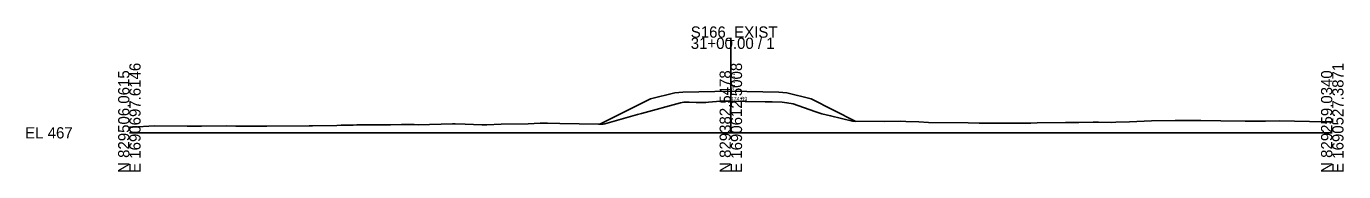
# Model space of a CAD drawing. Extents: x 1621104 to 1621433, y 1192880 to 1199414.
# Drawn here: x 1621104.2 to 1621432.7, y 1196379.5 to 1196415.8 of the extents above; entities that cross this region are included whole.
import ezdxf

# ---------------------------------------------------------------- set-up
doc = ezdxf.new("R2010")
doc.units = 0
for name, color, linetype in [('RD_GPK_XS_Cell', 7, 'Continuous'), ('RD_XS_EarthShd', 7, 'Continuous'), ('RD_XS_ExGround', 7, 'Continuous'), ('RD_XS_Pave', 7, 'Continuous'), ('RD_XS_TieSlope', 7, 'Continuous'), ('RD_XS_TX_Elev_EX', 7, 'Continuous'), ('RD_XS_TX_Elev_PR', 7, 'Continuous')]:
    doc.layers.add(name, color=color, linetype=linetype)

msp = doc.modelspace()

# ---------------------------------------------------------------- linework, layer by layer
at = {"layer": 'RD_GPK_XS_Cell'}
for p, q in [((1621279.86, 1196389.24), (1621279.86, 1196412.99)), ((1621129.86, 1196389.24), (1621279.86, 1196389.24)), ((1621279.86, 1196389.24), (1621429.86, 1196389.24))]:
    msp.add_line(p, q, dxfattribs=at)
at = {"layer": 'RD_XS_EarthShd'}
for p, q in [((1621267.86, 1196399.37), (1621265.86, 1196399.21)), ((1621291.86, 1196399.37), (1621293.86, 1196399.21))]:
    msp.add_line(p, q, dxfattribs=at)
at = {"layer": 'RD_XS_ExGround'}
msp.add_lwpolyline([(1621129.86, 1196390.64), (1621130.61, 1196390.68), (1621136.01, 1196390.97), (1621144.31, 1196390.87), (1621145.07, 1196390.87), (1621147.84, 1196390.89), (1621153.99, 1196390.95), (1621156.41, 1196390.92), (1621159.51, 1196390.9), (1621161.89, 1196390.88), (1621164.16, 1196390.92), (1621174.73, 1196390.96), (1621175.56, 1196390.99), (1621181.61, 1196391.1), (1621182.72, 1196391.15), (1621185.7, 1196391.18), (1621186.6, 1196391.24), (1621194.96, 1196391.25), (1621197.74, 1196391.28), (1621200.89, 1196391.31), (1621201.85, 1196391.26), (1621210.45, 1196391.48), (1621211.12, 1196391.48), (1621213.64, 1196391.37), (1621217.76, 1196391.21), (1621218.98, 1196391.21), (1621222.61, 1196391.37), (1621229.35, 1196391.49), (1621232.27, 1196391.62), (1621234.16, 1196391.63), (1621237.22, 1196391.55), (1621246.85, 1196391.39), (1621248.02, 1196391.38), (1621248.45, 1196391.5), (1621256.56, 1196393.79), (1621257.56, 1196394.03), (1621267.29, 1196396.73), (1621268.11, 1196396.88), (1621269.43, 1196396.9), (1621271.22, 1196396.84), (1621273.61, 1196396.83), (1621274.31, 1196396.86), (1621277.32, 1196397.15), (1621279.86, 1196397.12), (1621283.42, 1196397.08), (1621283.83, 1196397.08), (1621288.45, 1196396.94), (1621290.15, 1196396.97), (1621292.68, 1196396.91), (1621293.84, 1196396.76), (1621295.42, 1196396.46), (1621300.8, 1196394.59), (1621302.55, 1196393.96), (1621304.75, 1196393.49), (1621310.23, 1196392.12), (1621318.08, 1196392.06), (1621322.23, 1196392.14), (1621323.52, 1196392.1), (1621326.76, 1196391.97), (1621329.19, 1196391.79), (1621339.06, 1196391.74), (1621341.82, 1196391.66), (1621344.79, 1196391.69), (1621349.9, 1196391.66), (1621351.13, 1196391.64), (1621354.7, 1196391.67), (1621356.27, 1196391.71), (1621363.32, 1196391.81), (1621363.97, 1196391.81), (1621366.62, 1196391.86), (1621370.2, 1196391.93), (1621371.52, 1196391.89), (1621374.89, 1196391.79), (1621375.86, 1196391.88), (1621379.33, 1196392.01), (1621384.74, 1196392.26), (1621390.71, 1196392.32), (1621394.98, 1196392.33), (1621397.1, 1196392.29), (1621402.05, 1196392.24), (1621408.1, 1196392.13), (1621413.22, 1196392.18), (1621416.59, 1196392.22), (1621427.97, 1196391.98), (1621429.86, 1196391.95)], dxfattribs=at)
at = {"layer": 'RD_XS_Pave'}
for p, q in [((1621267.86, 1196399.37), (1621279.86, 1196399.61)), ((1621279.86, 1196399.61), (1621291.86, 1196399.37))]:
    msp.add_line(p, q, dxfattribs=at)
at = {"layer": 'RD_XS_TieSlope'}
for p, q in [((1621259.86, 1196397.71), (1621247.2, 1196391.38)), ((1621265.86, 1196399.21), (1621259.86, 1196397.71)), ((1621293.86, 1196399.21), (1621299.86, 1196397.71)), ((1621299.86, 1196397.71), (1621311.05, 1196392.11))]:
    msp.add_line(p, q, dxfattribs=at)

# ---------------------------------------------------------------- texts
at = {"layer": 'RD_GPK_XS_Cell'}
for s, p in [('S166_EXIST', (1621269.86, 1196412.99)), ('31+00.00 / 1', (1621269.86, 1196410.19)), ('EL 467', (1621103.86, 1196387.84))]:
    msp.add_text(s, height=2.8, dxfattribs=at).set_placement(p)
for s, p in [('N 829506.0615', (1621129.86, 1196379.24)), ('E 1690697.6146', (1621132.66, 1196379.24)), ('N 829382.5478', (1621279.86, 1196379.24)), ('E 1690612.5008', (1621282.66, 1196379.24)), ('N 829259.0340', (1621429.86, 1196379.24)), ('E 1690527.3871', (1621432.66, 1196379.24))]:
    msp.add_text(s, height=2.8, rotation=90, dxfattribs=at).set_placement(p)
at = {"layer": 'RD_XS_TX_Elev_EX'}
msp.add_text('474.89', height=1, dxfattribs=at).set_placement((1621279.76, 1196397.22))
at = {"layer": 'RD_XS_TX_Elev_PR'}
msp.add_text(' 477.37', height=1, rotation=90, dxfattribs=at).set_placement((1621280.86, 1196399.61))

doc.saveas('drawing.dxf')
